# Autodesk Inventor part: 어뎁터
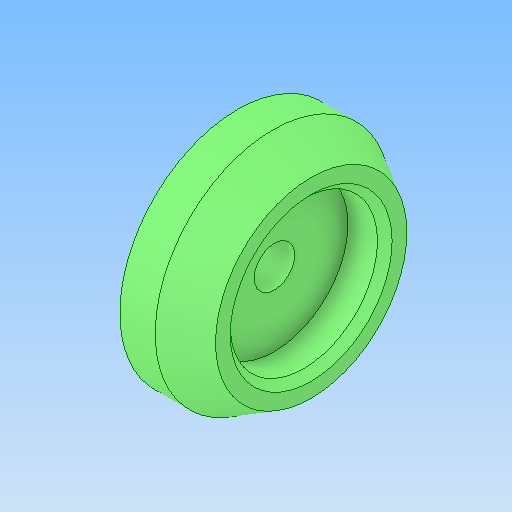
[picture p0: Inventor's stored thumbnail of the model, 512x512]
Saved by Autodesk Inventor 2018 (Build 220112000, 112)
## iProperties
Created: 2024-09
Part Number: 어뎁터
Material: 강철, 탄소
Document SubType Name: Modeling
Designer: home
Density: 7.85 g/cm^3
Appearance: 기본값
Author: jhkim
Sending System: Autodesk Inventor 2025
Preprocessor: ST-DEVELOPER v20
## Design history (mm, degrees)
feature "솔리드1"
node "솔리드2"
